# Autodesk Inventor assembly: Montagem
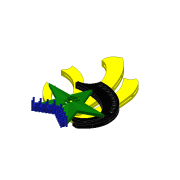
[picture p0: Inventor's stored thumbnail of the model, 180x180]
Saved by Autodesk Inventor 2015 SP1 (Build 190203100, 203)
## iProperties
Created: 2015-04
Part Number: Montagem
Document SubType Name: Assembly
Designer: TREINA9
Author: TREINA9
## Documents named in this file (5)
- C:\Users\sn1018289\Desktop\WSI2015 - Visitor Experience Project\#27- Jewellry\01- 3D Models\Inventor files\Assembly.iam
- C:\Users\sn1018289\Desktop\WSI2015 - Visitor Experience Project\#27- Jewellry\01- 3D Models\Inventor files\Module 1.ipt
- C:\Users\sn1018289\Desktop\WSI2015 - Visitor Experience Project\#27- Jewellry\01- 3D Models\Inventor files\Module 2.ipt
- C:\Users\sn1018289\Desktop\WSI2015 - Visitor Experience Project\#27- Jewellry\01- 3D Models\Inventor files\Module 3.ipt
- C:\Users\sn1018289\Desktop\WSI2015 - Visitor Experience Project\#27- Jewellry\01- 3D Models\Inventor files\Module 4.ipt
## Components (4 placed, 4 different names)
1. Module 2:1 — Flush:1, Flush:2, Flush:3, Flush:4, Flush:5, Flush:6, Flush:7, Flush:8, Flush:9
2. Module 1:1 — Flush:7, Flush:8, Flush:9, Flush:10, Flush:11, Flush:12
3. Module 3:1 — Flush:4, Flush:5, Flush:6
4. Module 4:1 — Flush:10, Flush:11, Flush:12
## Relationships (12: Flush 12)
- Flush:1: Module 2:1
- Flush:2: Module 2:1
- Flush:3: Module 2:1
- Flush:4: Module 2:1 ↔ Module 3:1
- Flush:5: Module 2:1 ↔ Module 3:1
- Flush:6: Module 2:1 ↔ Module 3:1
- Flush:7: Module 2:1 ↔ Module 1:1
- Flush:8: Module 2:1 ↔ Module 1:1
- Flush:9: Module 2:1 ↔ Module 1:1
- Flush:10: Module 1:1 ↔ Module 4:1
- Flush:11: Module 1:1 ↔ Module 4:1
- Flush:12: Module 1:1 ↔ Module 4:1
